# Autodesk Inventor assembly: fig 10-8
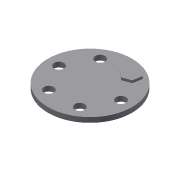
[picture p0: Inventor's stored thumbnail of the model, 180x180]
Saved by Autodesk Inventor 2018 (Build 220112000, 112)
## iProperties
Created: 2008-05
Part Number: fig 10-8
Document SubType Name: Assembly
Designer: CADCIM
Author: CADCIM
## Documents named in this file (3)
- E:\_Deepak\Inventor\Autodesk Inventor_2017_Project\Resources\Inventor_2018_Part\c10_Inv_2018\c10_inv_2018_prt\fig 10-8.iam
- E:\_Deepak\Inventor\Autodesk Inventor_2017_Project\Resources\Inventor_2018_Part\c10_Inv_2018\c10_inv_2018_prt\Part4.ipt
- E:\_Deepak\Inventor\Autodesk Inventor_2017_Project\Resources\Inventor_2018_Part\c10_Inv_2018\c10_inv_2018_prt\Part5.ipt
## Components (2 placed, 2 different names)
1. Part4:1 — Insert:1
2. Part5:1 — Insert:1
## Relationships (1: Insert 1)
- Insert:1: Part4:1 ↔ Part5:1
